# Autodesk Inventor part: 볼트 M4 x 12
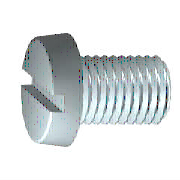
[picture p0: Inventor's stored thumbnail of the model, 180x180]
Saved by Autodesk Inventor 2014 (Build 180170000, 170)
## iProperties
Created: 2012-02
Part Number: 볼트 M4 x 12
Material: 강철, 연강
Description: 6각머리 태핑 나사
Document SubType Name: Modeling
Standard: KS B 1021
Designer: mduedu
Standards Organization: KS
Language: ko-KR
Size Designation: A  M 4 x 12
Categories: <MemberInstance><Categories><Category DisplayName="조임쇠" InternalName="e4da775c-781d-43d5-af7c-5136215cf5a6" Mnemonic="FSTN"><Category DisplayName="볼트" InternalN
Density: 1 g/cm^3
Appearance: 강철
IsCustomPart: 0
Author: mduedu
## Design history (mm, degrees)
body "Solid1"
revolve "본체" stored, may be unused: angle "d8" = 90 deg
sketch "스케치2"
  geometry: L1 (0, 0)-(0, 3.273) reference; L2 (-3.5, 0.6)-(3.5, 0.6); L3 (3.5, 0.6)-(3.5, -0.6); L4 (3.5, -0.6)-(-3.5, -0.6); L5 (-3.5, -0.6)-(-3.5, 0.6); L6 (-3.5, 0)-(3.5, 0); L7 (0, 0.6)-(0, -0.6); C1 r 3.5 at (0, 0) reference; 1 further point
  constraints: 12 end point, 5 midpoint, 2 parallel, 1 collinear, 1 horizontal, 1 perpendicular
  dimensions: "d11" = 1.2 distance of L4.end L2.start (= SBR); "d12" = 7 distance of L2.start L2.end (= KOD)
fillet "모깎기1" dims "d14" = 0.2 (= RR)
extrude "슬롯" cut sketch "스케치2" distance "d19" = 1.1 (= STI); taper "d20" = 0 deg
feature "스레드" dims "d15" = 10.6 (= GEL), "d16" = 0
chamfer "모따기1" distance "d17" = 0.42941 (= -0.5 x SPD + 0.5 x GD); stored, may be unused: second distance "d18" = 0.42952 (computed from GUL), angle "d36" = 45 deg
workplane "Work Plane1"
sketch "스케치1"
  geometry: L1 (-2.6, 0)-(12, 0); L2 (12, 0)-(12, 2); L3 (12, 2)-(1.4, 2); L4 (1.4, 2)-(0.97, 1.785); L5 (0.97, 1.785)-(0, 1.785); L6 (0, 1.785)-(0, 3.5); L7 (-5.52, 0)-(14.92, 0) reference; L8 (0, -0.7)-(0, 4.2) reference; L9 (-2.6, 0)-(-2.6, 3.273); L10 (0, 3.5)-(-2.6, 3.273); L11 (1.4, 2)-(0, 2)
  constraints: 18 end point, 4 parallel, 2 collinear, 2 perpendicular, 1 horizontal, 1 point on line
  dimensions: "d0" = 12 distance between parallel lines of L2 L6 (= NLG); "d1" = 10.6 distance from line of L3.end L2 (= GEL); "d2" = 0.42952 horizontal distance of L4.end L3.end (computed from GAL); "d3" = 2.6 distance from line of L1.start L6 (= KOH); "d4" = 4 diameter of L3 L1 (= GD); "d5" = 3.5705 diameter of L5 L1 (= BDM); "d9" = 7 diameter of L6.end L1 (= KOD); "d10" = 5 deg angle of L10 L1 (= KEWI)
other parameters: "GD" = 4 (= NND) [user parameter; used in 2 equation terms], "NLG" = 12 [user parameter; used in 1 equation term], "GEL" = 10.6 [user parameter; used in 2 equation terms], "KOD" = 7 [user parameter; used in 2 equation terms], "KOH" = 2.6 [user parameter; used in 1 equation term], "GAL" = 0.42941 (= 0.61345 x PTC) [user parameter; used in 1 equation term], "SPD" = 3.14117 (= NND - 1.2269 x PTC) [user parameter; used in 1 equation term], "BDM" = 3.5705 [user parameter; used in 1 equation term], "GUL" = 0.42941 (= 0.61345 x PTC) [user parameter; used in 1 equation term], "RR" = 0.2 [user parameter; used in 1 equation term], "d7" = 0, "SBR" = 1.2 [user parameter; used in 1 equation term], "STI" = 1.1 [user parameter; used in 1 equation term], "KEWI" = 5 deg [user parameter; used in 1 equation term], "d37" = 0, "d39" = 0, "PTC" = 0.7 [user parameter; used in 5 equation terms], "THREADDIA" = 4 [user parameter; used in 1 equation term], "TOA" = 30 deg [user parameter], "TPU" = 14.28571 (computed from PTC) [user parameter], "NND" = 4 [user parameter; used in 2 equation terms], "GD1" = 3.14117 (= THREADDIA - 1.2269 x PTC) [user parameter]
